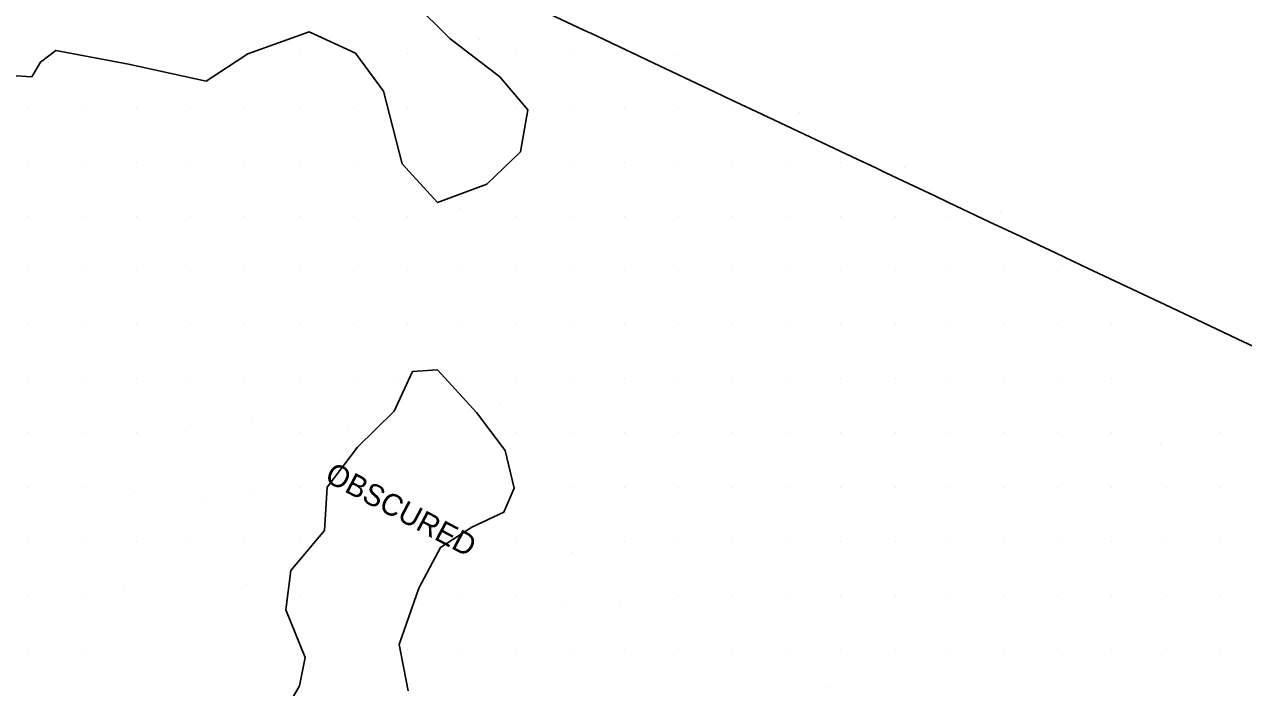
# Model space of a CAD drawing. Extents: x 1497074 to 1501343, y 481943 to 486114.
# Drawn here: x 1499353.3 to 1499690.7, y 483091.2 to 483274.9 of the extents above; entities that cross this region are included whole.
import ezdxf

# ---------------------------------------------------------------- set-up
doc = ezdxf.new("R2010")
doc.units = 0
for name, color, linetype in [('PH Exist DTM Boundary', 7, 'Continuous'), ('PH Exist DTM Obscure Area', 7, 'Continuous'), ('PH Exist DTM Obscure Area Text', 7, 'Continuous'), ('PH Exist DTM Point', 7, 'Continuous')]:
    doc.layers.add(name, color=color, linetype=linetype)

msp = doc.modelspace()

# ---------------------------------------------------------------- linework, layer by layer
at = {"layer": 'PH Exist DTM Boundary'}
msp.add_lwpolyline([(1499696.2, 483184.38), (1499689.09, 483187.74), (1499681.16, 483191.49), (1499669.09, 483197.2), (1499658.27, 483202.31), (1499649.09, 483206.65), (1499645.81, 483208.21), (1499638.86, 483211.49), (1499629.09, 483216.11), (1499620.33, 483220.25), (1499609.09, 483225.57), (1499605.07, 483227.47), (1499596.56, 483231.49), (1499591.49, 483233.89), (1499589.09, 483235.02), (1499582.39, 483238.19), (1499569.09, 483244.48), (1499554.26, 483251.49), (1499549.09, 483253.93), (1499544.46, 483256.13), (1499529.09, 483263.39), (1499511.96, 483271.49), (1499510.01, 483272.41), (1499509.09, 483272.85), (1499506.52, 483274.06), (1499489.09, 483282.3)], dxfattribs=at)
at = {"layer": 'PH Exist DTM Obscure Area'}
for points in [[(1499431.58, 483316.16), (1499450.67, 483291.29), (1499471.05, 483270.93), (1499484.88, 483260.35), (1499492.57, 483251.23), (1499490.58, 483239.59), (1499481.24, 483230.65), (1499467.63, 483225.52), (1499457.84, 483236.22), (1499452.67, 483256.35), (1499444.92, 483266.94), (1499432.07, 483272.82), (1499415.07, 483266.68), (1499403.61, 483259.14), (1499382.1, 483263.83), (1499361.96, 483267.68), (1499357.73, 483264.42), (1499355.34, 483260.39), (1499349.51, 483260.77), (1499345.76, 483265.29)], [(1499424.54, 483083.2), (1499429.4, 483091.71), (1499431.01, 483099.6), (1499425.59, 483112.77), (1499427, 483123.63), (1499436.37, 483134.72), (1499437.1, 483146.7), (1499445.45, 483157.79), (1499455.65, 483167.82), (1499460.73, 483178.79), (1499467.63, 483179.19), (1499478.43, 483167.42), (1499486.34, 483156.93), (1499488.87, 483146.47), (1499486.01, 483139.84), (1499477.12, 483135.62)], [(1499477.12, 483135.62), (1499468.47, 483130.03), (1499462.48, 483118.76), (1499456.97, 483103.19), (1499459.45, 483090.38)]]:
    msp.add_lwpolyline(points, dxfattribs=at)
at = {"layer": 'PH Exist DTM Point'}
for p, q in [((1499479.36, 483270.82), (1499479.36, 483270.82)), ((1499369.29, 483266.76), (1499369.29, 483266.76)), ((1499429.29, 483266.76), (1499429.29, 483266.76)), ((1499444.29, 483266.76), (1499444.29, 483266.76)), ((1499459.29, 483266.76), (1499459.29, 483266.76)), ((1499489.29, 483266.76), (1499489.29, 483266.76)), ((1499504.29, 483266.76), (1499504.29, 483266.76)), ((1499519.29, 483266.76), (1499519.29, 483266.76)), ((1499359.96, 483264.31), (1499359.96, 483264.31)), ((1499534.12, 483266.32), (1499534.12, 483266.32)), ((1499354.29, 483251.76), (1499354.29, 483251.76)), ((1499369.29, 483251.76), (1499369.29, 483251.76)), ((1499384.29, 483251.76), (1499384.29, 483251.76)), ((1499399.29, 483251.76), (1499399.29, 483251.76)), ((1499414.29, 483251.76), (1499414.29, 483251.76)), ((1499429.29, 483251.76), (1499429.29, 483251.76)), ((1499444.29, 483251.76), (1499444.29, 483251.76)), ((1499459.29, 483251.76), (1499459.29, 483251.76)), ((1499489.29, 483251.76), (1499489.29, 483251.76)), ((1499504.29, 483251.76), (1499504.29, 483251.76)), ((1499519.29, 483251.76), (1499519.29, 483251.76)), ((1499534.29, 483251.76), (1499534.29, 483251.76)), ((1499549.29, 483251.76), (1499549.29, 483251.76)), ((1499567.94, 483250.51), (1499567.94, 483250.51)), ((1499354.29, 483236.76), (1499354.29, 483236.76)), ((1499369.29, 483236.76), (1499369.29, 483236.76)), ((1499384.29, 483236.76), (1499384.29, 483236.76)), ((1499399.29, 483236.76), (1499399.29, 483236.76)), ((1499414.29, 483236.76), (1499414.29, 483236.76)), ((1499429.29, 483236.76), (1499429.29, 483236.76)), ((1499444.29, 483236.76), (1499444.29, 483236.76)), ((1499459.29, 483236.76), (1499459.29, 483236.76)), ((1499489.29, 483236.76), (1499489.29, 483236.76)), ((1499504.29, 483236.76), (1499504.29, 483236.76)), ((1499519.29, 483236.76), (1499519.29, 483236.76)), ((1499534.29, 483236.76), (1499534.29, 483236.76)), ((1499549.29, 483236.76), (1499549.29, 483236.76)), ((1499564.29, 483236.76), (1499564.29, 483236.76)), ((1499579.29, 483236.76), (1499579.29, 483236.76)), ((1499596.8, 483235.21), (1499596.8, 483235.21)), ((1499474.08, 483223.76), (1499474.08, 483223.76)), ((1499623.38, 483222.66), (1499623.38, 483222.66)), ((1499354.29, 483221.76), (1499354.29, 483221.76)), ((1499369.29, 483221.76), (1499369.29, 483221.76)), ((1499384.29, 483221.76), (1499384.29, 483221.76)), ((1499399.29, 483221.76), (1499399.29, 483221.76)), ((1499414.29, 483221.76), (1499414.29, 483221.76)), ((1499429.29, 483221.76), (1499429.29, 483221.76)), ((1499444.29, 483221.76), (1499444.29, 483221.76)), ((1499459.29, 483221.76), (1499459.29, 483221.76)), ((1499489.29, 483221.76), (1499489.29, 483221.76)), ((1499504.29, 483221.76), (1499504.29, 483221.76)), ((1499519.29, 483221.76), (1499519.29, 483221.76)), ((1499534.29, 483221.76), (1499534.29, 483221.76)), ((1499549.29, 483221.76), (1499549.29, 483221.76)), ((1499564.29, 483221.76), (1499564.29, 483221.76)), ((1499579.29, 483221.76), (1499579.29, 483221.76)), ((1499594.29, 483221.76), (1499594.29, 483221.76)), ((1499609.29, 483221.76), (1499609.29, 483221.76)), ((1499354.29, 483206.76), (1499354.29, 483206.76)), ((1499369.29, 483206.76), (1499369.29, 483206.76)), ((1499384.29, 483206.76), (1499384.29, 483206.76)), ((1499399.29, 483206.76), (1499399.29, 483206.76)), ((1499414.29, 483206.76), (1499414.29, 483206.76)), ((1499429.29, 483206.76), (1499429.29, 483206.76)), ((1499444.29, 483206.76), (1499444.29, 483206.76)), ((1499459.29, 483206.76), (1499459.29, 483206.76)), ((1499474.29, 483206.76), (1499474.29, 483206.76)), ((1499489.29, 483206.76), (1499489.29, 483206.76)), ((1499504.29, 483206.76), (1499504.29, 483206.76)), ((1499519.29, 483206.76), (1499519.29, 483206.76)), ((1499534.29, 483206.76), (1499534.29, 483206.76)), ((1499549.29, 483206.76), (1499549.29, 483206.76)), ((1499564.29, 483206.76), (1499564.29, 483206.76)), ((1499579.29, 483206.76), (1499579.29, 483206.76)), ((1499594.29, 483206.76), (1499594.29, 483206.76)), ((1499609.29, 483206.76), (1499609.29, 483206.76)), ((1499624.29, 483206.76), (1499624.29, 483206.76)), ((1499639.29, 483206.76), (1499639.29, 483206.76)), ((1499670.67, 483198.46), (1499670.67, 483198.46)), ((1499354.29, 483191.76), (1499354.29, 483191.76)), ((1499369.29, 483191.76), (1499369.29, 483191.76)), ((1499384.29, 483191.76), (1499384.29, 483191.76)), ((1499399.29, 483191.76), (1499399.29, 483191.76)), ((1499414.29, 483191.76), (1499414.29, 483191.76)), ((1499429.29, 483191.76), (1499429.29, 483191.76)), ((1499444.29, 483191.76), (1499444.29, 483191.76)), ((1499459.29, 483191.76), (1499459.29, 483191.76)), ((1499474.29, 483191.76), (1499474.29, 483191.76)), ((1499489.29, 483191.76), (1499489.29, 483191.76)), ((1499504.29, 483191.76), (1499504.29, 483191.76)), ((1499519.29, 483191.76), (1499519.29, 483191.76)), ((1499534.29, 483191.76), (1499534.29, 483191.76)), ((1499549.29, 483191.76), (1499549.29, 483191.76)), ((1499564.29, 483191.76), (1499564.29, 483191.76)), ((1499579.29, 483191.76), (1499579.29, 483191.76)), ((1499594.29, 483191.76), (1499594.29, 483191.76)), ((1499609.29, 483191.76), (1499609.29, 483191.76)), ((1499624.29, 483191.76), (1499624.29, 483191.76)), ((1499639.29, 483191.76), (1499639.29, 483191.76)), ((1499654.29, 483191.76), (1499654.29, 483191.76)), ((1499354.29, 483176.76), (1499354.29, 483176.76)), ((1499369.29, 483176.76), (1499369.29, 483176.76)), ((1499384.29, 483176.76), (1499384.29, 483176.76)), ((1499399.29, 483176.76), (1499399.29, 483176.76)), ((1499414.29, 483176.76), (1499414.29, 483176.76)), ((1499429.29, 483176.76), (1499429.29, 483176.76)), ((1499444.29, 483176.76), (1499444.29, 483176.76)), ((1499455.63, 483176.09), (1499455.63, 483176.09)), ((1499474.29, 483176.76), (1499474.29, 483176.76)), ((1499489.29, 483176.76), (1499489.29, 483176.76)), ((1499504.29, 483176.76), (1499504.29, 483176.76)), ((1499519.29, 483176.76), (1499519.29, 483176.76)), ((1499534.29, 483176.76), (1499534.29, 483176.76)), ((1499549.29, 483176.76), (1499549.29, 483176.76)), ((1499564.29, 483176.76), (1499564.29, 483176.76)), ((1499579.29, 483176.76), (1499579.29, 483176.76)), ((1499594.29, 483176.76), (1499594.29, 483176.76)), ((1499609.29, 483176.76), (1499609.29, 483176.76)), ((1499624.29, 483176.76), (1499624.29, 483176.76)), ((1499639.29, 483176.76), (1499639.29, 483176.76)), ((1499654.29, 483176.76), (1499654.29, 483176.76)), ((1499484.88, 483169.84), (1499484.88, 483169.84)), ((1499416.45, 483165.84), (1499416.45, 483165.84)), ((1499397.81, 483162.54), (1499397.81, 483162.54)), ((1499443.01, 483162.44), (1499443.01, 483162.44)), ((1499354.29, 483161.76), (1499354.29, 483161.76)), ((1499369.29, 483161.76), (1499369.29, 483161.76)), ((1499384.29, 483161.76), (1499384.29, 483161.76)), ((1499429.29, 483161.76), (1499429.29, 483161.76)), ((1499489.29, 483161.76), (1499489.29, 483161.76)), ((1499504.29, 483161.76), (1499504.29, 483161.76)), ((1499519.29, 483161.76), (1499519.29, 483161.76)), ((1499534.29, 483161.76), (1499534.29, 483161.76)), ((1499549.29, 483161.76), (1499549.29, 483161.76)), ((1499564.29, 483161.76), (1499564.29, 483161.76)), ((1499579.29, 483161.76), (1499579.29, 483161.76)), ((1499594.29, 483161.76), (1499594.29, 483161.76)), ((1499609.29, 483161.76), (1499609.29, 483161.76)), ((1499624.29, 483161.76), (1499624.29, 483161.76)), ((1499639.29, 483161.76), (1499639.29, 483161.76)), ((1499654.29, 483161.76), (1499654.29, 483161.76)), ((1499667.69, 483158.77), (1499667.69, 483158.77)), ((1499684.29, 483161.76), (1499684.29, 483161.76)), ((1499354.29, 483146.76), (1499354.29, 483146.76)), ((1499369.29, 483146.76), (1499369.29, 483146.76)), ((1499383.63, 483145.52), (1499383.63, 483145.52)), ((1499416.74, 483144.96), (1499416.74, 483144.96)), ((1499429.29, 483146.76), (1499429.29, 483146.76)), ((1499489.29, 483146.76), (1499489.29, 483146.76)), ((1499504.29, 483146.76), (1499504.29, 483146.76)), ((1499519.29, 483146.76), (1499519.29, 483146.76)), ((1499534.29, 483146.76), (1499534.29, 483146.76)), ((1499549.29, 483146.76), (1499549.29, 483146.76)), ((1499564.29, 483146.76), (1499564.29, 483146.76)), ((1499579.29, 483146.76), (1499579.29, 483146.76)), ((1499594.29, 483146.76), (1499594.29, 483146.76)), ((1499609.29, 483146.76), (1499609.29, 483146.76)), ((1499624.29, 483146.76), (1499624.29, 483146.76)), ((1499639.29, 483146.76), (1499639.29, 483146.76)), ((1499654.29, 483146.76), (1499654.29, 483146.76)), ((1499669.29, 483146.76), (1499669.29, 483146.76)), ((1499684.29, 483146.76), (1499684.29, 483146.76)), ((1499402.52, 483143.99), (1499402.52, 483143.99)), ((1499354.29, 483131.76), (1499354.29, 483131.76)), ((1499369.29, 483131.76), (1499369.29, 483131.76)), ((1499384.29, 483131.76), (1499384.29, 483131.76)), ((1499399.29, 483131.76), (1499399.29, 483131.76)), ((1499414.29, 483131.76), (1499414.29, 483131.76)), ((1499429.29, 483131.76), (1499429.29, 483131.76)), ((1499474.46, 483131.67), (1499474.46, 483131.67)), ((1499489.52, 483131.64), (1499489.52, 483131.64)), ((1499519.29, 483131.76), (1499519.29, 483131.76)), ((1499534.29, 483131.76), (1499534.29, 483131.76)), ((1499549.29, 483131.76), (1499549.29, 483131.76)), ((1499564.29, 483131.76), (1499564.29, 483131.76)), ((1499579.29, 483131.76), (1499579.29, 483131.76)), ((1499594.29, 483131.76), (1499594.29, 483131.76)), ((1499609.29, 483131.76), (1499609.29, 483131.76)), ((1499624.29, 483131.76), (1499624.29, 483131.76)), ((1499639.29, 483131.76), (1499639.29, 483131.76)), ((1499654.29, 483131.76), (1499654.29, 483131.76)), ((1499669.29, 483131.76), (1499669.29, 483131.76)), ((1499684.29, 483131.76), (1499684.29, 483131.76)), ((1499505.11, 483128.76), (1499505.11, 483128.76)), ((1499381.04, 483118.48), (1499381.04, 483118.48)), ((1499414.81, 483119.85), (1499414.81, 483119.85)), ((1499354.29, 483116.76), (1499354.29, 483116.76)), ((1499369.29, 483116.76), (1499369.29, 483116.76)), ((1499429.29, 483116.76), (1499429.29, 483116.76)), ((1499462.06, 483115.29), (1499462.06, 483115.29)), ((1499474.29, 483116.76), (1499474.29, 483116.76)), ((1499489.07, 483116.33), (1499489.07, 483116.33)), ((1499518.37, 483115.04), (1499518.37, 483115.04)), ((1499534.29, 483116.76), (1499534.29, 483116.76)), ((1499549.29, 483116.76), (1499549.29, 483116.76)), ((1499564.29, 483116.76), (1499564.29, 483116.76)), ((1499579.29, 483116.76), (1499579.29, 483116.76)), ((1499594.29, 483116.76), (1499594.29, 483116.76)), ((1499609.29, 483116.76), (1499609.29, 483116.76)), ((1499624.29, 483116.76), (1499624.29, 483116.76)), ((1499639.29, 483116.76), (1499639.29, 483116.76)), ((1499654.29, 483116.76), (1499654.29, 483116.76)), ((1499669.29, 483116.76), (1499669.29, 483116.76)), ((1499684.29, 483116.76), (1499684.29, 483116.76)), ((1499503.07, 483114.39), (1499503.07, 483114.39)), ((1499354.29, 483101.76), (1499354.29, 483101.76)), ((1499369.29, 483101.76), (1499369.29, 483101.76)), ((1499429.29, 483101.76), (1499429.29, 483101.76)), ((1499459.29, 483101.76), (1499459.29, 483101.76)), ((1499474.29, 483101.76), (1499474.29, 483101.76)), ((1499489.29, 483101.76), (1499489.29, 483101.76)), ((1499504.29, 483101.76), (1499504.29, 483101.76)), ((1499519.29, 483101.76), (1499519.29, 483101.76)), ((1499534.29, 483101.76), (1499534.29, 483101.76)), ((1499549.29, 483101.76), (1499549.29, 483101.76)), ((1499564.29, 483101.76), (1499564.29, 483101.76)), ((1499579.29, 483101.76), (1499579.29, 483101.76)), ((1499594.29, 483101.76), (1499594.29, 483101.76)), ((1499609.29, 483101.76), (1499609.29, 483101.76)), ((1499624.29, 483101.76), (1499624.29, 483101.76)), ((1499639.29, 483101.76), (1499639.29, 483101.76)), ((1499654.29, 483101.76), (1499654.29, 483101.76)), ((1499669.29, 483101.76), (1499669.29, 483101.76)), ((1499684.29, 483101.76), (1499684.29, 483101.76)), ((1499576.03, 483091.37), (1499576.03, 483091.37))]:
    msp.add_line(p, q, dxfattribs=at)

# ---------------------------------------------------------------- texts
at = {"layer": 'PH Exist DTM Obscure Area Text'}
msp.add_text('OBSCURED', height=6, rotation=332.0096, dxfattribs=at).set_placement((1499436.07, 483148.58))

doc.saveas('drawing.dxf')
